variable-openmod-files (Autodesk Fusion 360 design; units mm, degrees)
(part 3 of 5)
sketch "Sketch1" plane through (0, 0, 1.5) normal (0, 0, 1) x axis (-1, 0, 0)
  line L1 (-6.5, -117.4019) -> (-9.9868, -115.3888)
  line L2 (-1, -130.9545) -> (-1, -126.9282)
  line L3 (-1, -107.0385) -> (-1, -103.0294)
  line L4 (-14.1969, -110.6487) -> (-10.725, -112.6532)
  line L5 (5.5, -115.6699) -> (8.9868, -113.6567)
  line L6 (-8.9868, -113.6567) -> (-5.5, -115.6699)
  line L7 (1, -132.9615) -> (1, -136.9706)
  line L8 (14.1969, -129.3513) -> (10.725, -127.3468)
  line L9 (11.725, -125.6147) -> (15.1969, -127.6193)
  line L10 (15.1969, -112.3807) -> (11.725, -114.3853)
  line L11 (-11.725, -114.3853) -> (-15.1969, -112.3807)
  line L12 (-15.1969, -127.6193) -> (-11.725, -125.6147)
  line L13 (-10.725, -127.3468) -> (-14.1969, -129.3513)
  line L14 (-1, -136.9706) -> (-1, -132.9615)
  line L15 (10.725, -112.6532) -> (14.1969, -110.6487)
  line L16 (1, -103.0294) -> (1, -107.0385)
  line L17 (1, -126.9282) -> (1, -130.9545)
  line L18 (9.9868, -115.3888) -> (6.5, -117.4019)
  line L19 (-16.1795, -137.7263) -> (-12.9621, -133.8919)
  line L20 (-11.43, -135.1775) -> (-14.6475, -139.0119)
  line L21 (-1, -143.9792) -> (-1, -138.9737)
  line L22 (1, -138.9737) -> (1, -143.9792)
  line L23 (14.6475, -139.0119) -> (11.43, -135.1775)
  line L24 (12.9621, -133.8919) -> (16.1795, -137.7263)
  line L25 (23.4412, -125.1487) -> (18.5118, -124.2796)
  line L26 (18.8591, -122.3099) -> (23.7885, -123.1791)
  line L27 (21.2666, -108.8764) -> (16.9317, -111.3792)
  line L28 (15.9317, -109.6471) -> (20.2666, -107.1444)
  line L29 (9.141, -97.809) -> (7.4291, -102.5126)
  line L30 (5.5497, -101.8286) -> (7.2617, -97.1249)
  line L31 (-7.2617, -97.1249) -> (-5.5497, -101.8286)
  line L32 (-7.4291, -102.5126) -> (-9.141, -97.809)
  line L33 (-20.2666, -107.1444) -> (-15.9317, -109.6471)
  line L34 (-16.9317, -111.3792) -> (-21.2666, -108.8764)
  line L35 (-23.7885, -123.1791) -> (-18.8591, -122.3099)
  line L36 (-18.5118, -124.2796) -> (-23.4412, -125.1487)
  arc A1 centre (0, -120) radius 7 clockwise from (-1, -126.9282) to (-6.5, -117.4019)
  arc A2 centre (0, -120) radius 11 clockwise from (-1, -130.9545) to (-9.9868, -115.3888)
  arc A3 centre (0, -120) radius 13 clockwise from (-10.725, -112.6532) to (-1, -107.0385)
  arc A4 centre (0, -120) radius 17 clockwise from (-14.1969, -110.6487) to (-1, -103.0294)
  circle C1 centre (0, -120) radius 5
  arc A5 centre (0, -120) radius 7 clockwise from (-5.5, -115.6699) to (5.5, -115.6699)
  arc A6 centre (0, -120) radius 11 clockwise from (-8.9868, -113.6567) to (8.9868, -113.6567)
  arc A7 centre (0, -120) radius 13 clockwise from (10.725, -127.3468) to (1, -132.9615)
  arc A8 centre (0, -120) radius 17 clockwise from (14.1969, -129.3513) to (1, -136.9706)
  arc A9 centre (0, -120) radius 17 clockwise from (15.1969, -112.3807) to (15.1969, -127.6193)
  arc A10 centre (0, -120) radius 13 clockwise from (11.725, -114.3853) to (11.725, -125.6147)
  arc A11 centre (0, -120) radius 17 clockwise from (-15.1969, -127.6193) to (-15.1969, -112.3807)
  arc A12 centre (0, -120) radius 13 clockwise from (-11.725, -125.6147) to (-11.725, -114.3853)
  arc A13 centre (0, -120) radius 17 clockwise from (-1, -136.9706) to (-14.1969, -129.3513)
  arc A14 centre (0, -120) radius 13 clockwise from (-1, -132.9615) to (-10.725, -127.3468)
  arc A15 centre (0, -120) radius 17 clockwise from (1, -103.0294) to (14.1969, -110.6487)
  arc A16 centre (0, -120) radius 13 clockwise from (1, -107.0385) to (10.725, -112.6532)
  arc A17 centre (0, -120) radius 7 clockwise from (6.5, -117.4019) to (1, -126.9282)
  arc A18 centre (0, -120) radius 11 clockwise from (9.9868, -115.3888) to (1, -130.9545)
  arc A19 centre (0, -120) radius 19 clockwise from (-12.9621, -133.8919) to (-18.5118, -124.2796)
  arc A20 centre (0, -120) radius 24 clockwise from (-14.6475, -139.0119) to (-16.1795, -137.7263)
  arc A21 centre (0, -120) radius 19 clockwise from (-1, -138.9737) to (-11.43, -135.1775)
  arc A22 centre (0, -120) radius 24 clockwise from (1, -143.9792) to (-1, -143.9792)
  arc A23 centre (0, -120) radius 19 clockwise from (11.43, -135.1775) to (1, -138.9737)
  arc A24 centre (0, -120) radius 24 clockwise from (16.1795, -137.7263) to (14.6475, -139.0119)
  arc A25 centre (0, -120) radius 19 clockwise from (18.5118, -124.2796) to (12.9621, -133.8919)
  arc A26 centre (0, -120) radius 24 clockwise from (23.7885, -123.1791) to (23.4412, -125.1487)
  arc A27 centre (0, -120) radius 19 clockwise from (16.9317, -111.3792) to (18.8591, -122.3099)
  arc A28 centre (0, -120) radius 24 clockwise from (20.2666, -107.1444) to (21.2666, -108.8764)
  arc A29 centre (0, -120) radius 19 clockwise from (7.4291, -102.5126) to (15.9317, -109.6471)
  arc A30 centre (0, -120) radius 24 clockwise from (7.2617, -97.1249) to (9.141, -97.809)
  arc A31 centre (0, -120) radius 19 clockwise from (-5.5497, -101.8286) to (5.5497, -101.8286)
  arc A32 centre (0, -120) radius 24 clockwise from (-9.141, -97.809) to (-7.2617, -97.1249)
  arc A33 centre (0, -120) radius 19 clockwise from (-15.9317, -109.6471) to (-7.4291, -102.5126)
  arc A34 centre (0, -120) radius 24 clockwise from (-21.2666, -108.8764) to (-20.2666, -107.1444)
  arc A35 centre (0, -120) radius 19 clockwise from (-18.8591, -122.3099) to (-16.9317, -111.3792)
  arc A36 centre (0, -120) radius 24 clockwise from (-23.4412, -125.1487) to (-23.7885, -123.1791)
  circle C2 centre (0, -120) radius 19
  concentric A1 C2
  dimension "d412" diameter C2 = 38
extrude "Extrude1" cut sketch "Sketch1" profile of L19 A20 L20 L21 A22 L22 L23 A24 L24 L25 A26 L26 L27 A28 L28 L29 A30 L30 L31 A32 L32 L33 A34 L34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 against normal blind 1.5 bodies "Pad Mount (1)"
sketch "Sketch2" plane through (0, 0, 0) normal (0, 0, -1) x axis (1, 0, 0)
  line L1 (9.9868, -115.3888) -> (6.5, -117.4019)
  line L2 (1, -126.9282) -> (1, -130.9545)
  line L3 (1, -103.0294) -> (1, -107.0385)
  line L4 (10.725, -112.6532) -> (14.1969, -110.6487)
  line L5 (-8.9868, -113.6567) -> (-5.5, -115.6699)
  line L6 (5.5, -115.6699) -> (8.9868, -113.6567)
  line L7 (-1, -136.9706) -> (-1, -132.9615)
  line L8 (-10.725, -127.3468) -> (-14.1969, -129.3513)
  line L9 (-11.725, -114.3853) -> (-15.1969, -112.3807)
  line L10 (-15.1969, -127.6193) -> (-11.725, -125.6147)
  line L11 (11.725, -125.6147) -> (15.1969, -127.6193)
  line L12 (15.1969, -112.3807) -> (11.725, -114.3853)
  line L13 (1, -132.9615) -> (1, -136.9706)
  line L14 (14.1969, -129.3513) -> (10.725, -127.3468)
  line L15 (-1, -107.0385) -> (-1, -103.0294)
  line L16 (-14.1969, -110.6487) -> (-10.725, -112.6532)
  line L17 (-1, -130.9545) -> (-1, -126.9282)
  line L18 (-6.5, -117.4019) -> (-9.9868, -115.3888)
  circle C1 centre (0, -120) radius 19
  arc A1 centre (0, -120) radius 11 clockwise from (9.9868, -115.3888) to (1, -130.9545)
  arc A2 centre (0, -120) radius 7 clockwise from (6.5, -117.4019) to (1, -126.9282)
  arc A3 centre (0, -120) radius 17 clockwise from (1, -103.0294) to (14.1969, -110.6487)
  arc A4 centre (0, -120) radius 13 clockwise from (1, -107.0385) to (10.725, -112.6532)
  circle C2 centre (0, -120) radius 5
  arc A5 centre (0, -120) radius 11 clockwise from (-8.9868, -113.6567) to (8.9868, -113.6567)
  arc A6 centre (0, -120) radius 7 clockwise from (-5.5, -115.6699) to (5.5, -115.6699)
  arc A7 centre (0, -120) radius 17 clockwise from (-1, -136.9706) to (-14.1969, -129.3513)
  arc A8 centre (0, -120) radius 13 clockwise from (-1, -132.9615) to (-10.725, -127.3468)
  arc A9 centre (0, -120) radius 17 clockwise from (-15.1969, -127.6193) to (-15.1969, -112.3807)
  arc A10 centre (0, -120) radius 13 clockwise from (-11.725, -125.6147) to (-11.725, -114.3853)
  arc A11 centre (0, -120) radius 17 clockwise from (15.1969, -112.3807) to (15.1969, -127.6193)
  arc A12 centre (0, -120) radius 13 clockwise from (11.725, -114.3853) to (11.725, -125.6147)
  arc A13 centre (0, -120) radius 17 clockwise from (14.1969, -129.3513) to (1, -136.9706)
  arc A14 centre (0, -120) radius 13 clockwise from (10.725, -127.3468) to (1, -132.9615)
  arc A15 centre (0, -120) radius 17 clockwise from (-14.1969, -110.6487) to (-1, -103.0294)
  arc A16 centre (0, -120) radius 13 clockwise from (-10.725, -112.6532) to (-1, -107.0385)
  arc A17 centre (0, -120) radius 11 clockwise from (-1, -130.9545) to (-9.9868, -115.3888)
  arc A18 centre (0, -120) radius 7 clockwise from (-1, -126.9282) to (-6.5, -117.4019)
  circle C3 centre (0, -120) radius 24
  circle C4 centre (0, -120) radius 20.5
  concentric C1 C3
  concentric C1 C4
  dimension "d415" diameter C3 = 48
  dimension "d416" diameter C4 = 41
extrude "Extrude2" add sketch "Sketch2" profile of C3 C4 against normal blind 2.5
extrude "Extrude3" add of existing geometry blind 2.5
extrude "Extrude4" add sketch "Sketch2" profile of C1 C4 against normal blind 2.5 bodies "Pad Mount (1)"
delete_face "DeleteFace1"
extrude "Extrude5" cut of existing geometry blind -4
sketch "Sketch3" plane through (0, 0, 22) normal (0, 0, 1) x axis (-1, 0, 0)
  line L1 (27.3973, -100.8162) -> (24.0432, -103.1648)
  line L2 (24.0432, -136.8352) -> (27.3973, -139.1838)
  line L3 (-8, -87.4692) -> (-8, -96.1036)
  line L4 (8, -96.1036) -> (8, -87.4692)
  line L5 (-27.3973, -139.1838) -> (-24.0432, -136.8352)
  line L6 (-24.0432, -103.1648) -> (-27.3973, -100.8162)
  line L7 (-8, -65.8761) -> (-8, -68.1306)
  line L8 (8, -68.1306) -> (8, -65.8761)
  line L9 (17.2573, -73.968) -> (18.1032, -72.1557)
  line L10 (6, -66.9692) -> (6, -69.7523)
  line L11 (-6, -66.9692) -> (6, -66.9692)
  line L12 (-6, -69.7523) -> (-6, -66.9692)
  line L13 (-18.1032, -72.1557) -> (-17.2573, -73.968)
  line L14 (-15.6326, -145.0174) -> (-17.7523, -148.4096)
  line L15 (17.7523, -148.4096) -> (15.6326, -145.0174)
  line L16 (8, -97) -> (8, -96.1036)
  line L17 (8, -101.1254) -> (8, -97)
  line L18 (-8, -101.1254) -> (-8, -96.1036)
  line L19 (20.5, -120) -> (0, -120)
  line L20 (15.9099, -104.0901) -> (0, -120)
  line L21 (22.5, -120) -> (0, -120)
  line L22 (-15.9099, -104.0901) -> (0, -120)
  line L23 (-22.5, -120) -> (0, -120)
  line L24 (44.7744, -114.5) -> (37, -114.5)
  line L25 (-37, -114.5) -> (-44.7744, -114.5)
  line L26 (-37, -125.5) -> (-37, -114.5)
  line L27 (-44.7744, -125.5) -> (-37, -125.5)
  line L28 (37, -125.5) -> (44.7744, -125.5)
  line L29 (37, -114.5) -> (37, -125.5)
  line L30 (40.4204, -134.6184) -> (31.8667, -135.2833)
  line L31 (40.0904, -135.7159) -> (40.4204, -134.6184)
  line L32 (33.9261, -136.0336) -> (40.0904, -135.7159)
  curve K1 (32.5509, -136.0589) -> (33.9261, -136.0336)
  curve K2 (33.681, -136.8488) -> (32.5509, -136.0589)
  line L33 (38.6244, -140.5917) -> (33.681, -136.8488)
  line L34 (38.3133, -141.6264) -> (38.6244, -140.5917)
  line L35 (31.554, -136.3233) -> (38.3133, -141.6264)
  line L36 (31.8667, -135.2833) -> (31.554, -136.3233)
  line L37 (30.457, -152.0325) -> (25.6804, -148.7507)
  line L38 (29.9007, -152.8421) -> (30.457, -152.0325)
  line L39 (25.1241, -149.5603) -> (29.9007, -152.8421)
  line L40 (25.6804, -148.7507) -> (25.1241, -149.5603)
  line L41 (-27.2839, -159.541) -> (-19.3124, -156.3956)
  line L42 (-28.0551, -158.7007) -> (-27.2839, -159.541)
  line L43 (-24.3746, -150.8793) -> (-28.0551, -158.7007)
  line L44 (-23.5592, -151.7679) -> (-24.3746, -150.8793)
  line L45 (-24.7134, -154.0936) -> (-23.5592, -151.7679)
  line L46 (-22.4517, -156.5582) -> (-24.7134, -154.0936)
  line L47 (-20.0725, -155.5673) -> (-22.4517, -156.5582)
  line L48 (-19.3124, -156.3956) -> (-20.0725, -155.5673)
  line L49 (-35.6785, -142.0432) -> (-30.2699, -139.9615)
  line L50 (-36.0313, -141.1265) -> (-35.6785, -142.0432)
  line L51 (-30.6227, -139.0448) -> (-36.0313, -141.1265)
  line L52 (-30.2699, -139.9615) -> (-30.6227, -139.0448)
  line L53 (-37.736, -142.8351) -> (-36.6818, -142.4293)
  line L54 (-38.0888, -141.9183) -> (-37.736, -142.8351)
  line L55 (-37.0346, -141.5126) -> (-38.0888, -141.9183)
  line L56 (-36.6818, -142.4293) -> (-37.0346, -141.5126)
  line L57 (-18.3117, -159.6909) -> (-17.5657, -160.3171)
  curve K3 (-16.7865, -158.8106) -> (-18.3117, -159.6909)
  curve K4 (-15.133, -159.1979) -> (-16.7865, -158.8106)
  curve K5 (-13.9409, -160.8837) -> (-15.133, -159.1979)
  curve K6 (-14.5331, -163.1512) -> (-13.9409, -160.8837)
  curve K7 (-15.6803, -164.3672) -> (-14.5331, -163.1512)
  curve K8 (-17.0469, -164.7465) -> (-15.6803, -164.3672)
  curve K9 (-18.4019, -164.2975) -> (-17.0469, -164.7465)
  curve K10 (-19.4455, -163.063) -> (-18.4019, -164.2975)
  curve K11 (-19.3628, -161.506) -> (-19.4455, -163.063)
  line L58 (-18.479, -161.8966) -> (-19.3628, -161.506)
  curve K12 (-18.5456, -162.8969) -> (-18.479, -161.8966)
  curve K13 (-17.9988, -163.5965) -> (-18.5456, -162.8969)
  curve K14 (-16.6962, -163.7983) -> (-17.9988, -163.5965)
  curve K15 (-15.3982, -162.6301) -> (-16.6962, -163.7983)
  curve K16 (-14.8606, -160.9594) -> (-15.3982, -162.6301)
  curve K17 (-15.559, -159.8841) -> (-14.8606, -160.9594)
  curve K18 (-16.5638, -159.6624) -> (-15.559, -159.8841)
  curve K19 (-17.5657, -160.3171) -> (-16.5638, -159.6624)
  curve K20 (29.3301, -142.3161) -> (29.4979, -143.5426)
  curve K21 (29.5989, -141.2495) -> (29.3301, -142.3161)
  curve K22 (30.6252, -140.1009) -> (29.5989, -141.2495)
  curve K23 (31.923, -140.1206) -> (30.6252, -140.1009)
  curve K24 (32.5534, -140.6155) -> (31.923, -140.1206)
  curve K25 (32.8611, -141.3096) -> (32.5534, -140.6155)
  curve K26 (32.8658, -142.0862) -> (32.8611, -141.3096)
  curve K27 (32.6431, -142.9432) -> (32.8658, -142.0862)
  curve K28 (32.2353, -144.68) -> (32.6431, -142.9432)
  curve K29 (32.4671, -144.7899) -> (32.2353, -144.68)
  curve K30 (33.3528, -144.882) -> (32.4671, -144.7899)
  curve K31 (34.1141, -143.9973) -> (33.3528, -144.882)
  curve K32 (34.3111, -142.9643) -> (34.1141, -143.9973)
  curve K33 (33.7266, -142.1671) -> (34.3111, -142.9643)
  line L59 (34.239, -141.3443) -> (33.7266, -142.1671)
  curve K34 (34.9714, -142.145) -> (34.239, -141.3443)
  curve K35 (35.1493, -143.1756) -> (34.9714, -142.145)
  curve K36 (34.7981, -144.4594) -> (35.1493, -143.1756)
  curve K37 (34.1454, -145.4885) -> (34.7981, -144.4594)
  curve K38 (33.4655, -145.9312) -> (34.1454, -145.4885)
  curve K39 (32.7305, -145.9366) -> (33.4655, -145.9312)
  curve K40 (31.8838, -145.6108) -> (32.7305, -145.9366)
  line L60 (30.6887, -145.0751) -> (31.8838, -145.6108)
  curve K41 (29.082, -144.4236) -> (30.6887, -145.0751)
  curve K42 (28.3455, -144.3655) -> (29.082, -144.4236)
  line L61 (28.7652, -143.4294) -> (28.3455, -144.3655)
  curve K43 (29.4979, -143.5426) -> (28.7652, -143.4294)
  curve K44 (-36.4141, -138.56) -> (-33.8745, -138.7564)
  curve K45 (-37.5395, -136.9883) -> (-36.4141, -138.56)
  curve K46 (-37.3306, -134.894) -> (-37.5395, -136.9883)
  curve K47 (-35.4632, -133.5636) -> (-37.3306, -134.894)
  curve K48 (-33.6794, -133.3966) -> (-35.4632, -133.5636)
  curve K49 (-32.4511, -134.0579) -> (-33.6794, -133.3966)
  curve K50 (-31.7211, -135.3037) -> (-32.4511, -134.0579)
  curve K51 (-31.9236, -137.4104) -> (-31.7211, -135.3037)
  curve K52 (-33.8745, -138.7564) -> (-31.9236, -137.4104)
  line L62 (20.5824, -155.057) -> (19.8923, -155.6522)
  line L63 (25.8075, -161.1149) -> (20.5824, -155.057)
  line L64 (25.0636, -161.7565) -> (25.8075, -161.1149)
  line L65 (23.1996, -159.5953) -> (25.0636, -161.7565)
  curve K53 (22.5068, -161.2234) -> (23.1996, -159.5953)
  curve K54 (21.5994, -161.7213) -> (22.5068, -161.2234)
  curve K55 (20.6088, -161.7759) -> (21.5994, -161.7213)
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  point P10 (8, -96.1036)
  point P40 (8, -96.1036)
  point P9 (-8, -96.1036)
  point P43 (-8, -96.1036)
  point P4 (0, -120)
  point P46 (0, -120)
  point P49 (0, -120)
  point P45 (0, -120)
  point P52 (0, -120)
  coincident P10 P40
  parallel L4 L17
  coincident P9 P43
  parallel L3 L18
  horizontal L19
  coincident P4 P46
  horizontal L21
  coincident P4 P49
  horizontal L23
  coincident P45 P52
  dimension "d425" diameter = 41
  dimension "d426" diameter = 32
  dimension "d428" diameter = 45
  dimension "d429" angle L20 L21 = 45
  dimension "d430" angle L22 L23 = 45
extrude "Extrude6" add sketch "Sketch3" against normal blind 2
extrude "Extrude7" add sketch "Sketch3" along normal blind 4
chamfer "Chamfer1" distance 4.5 Rotate Angle 40
chamfer "Chamfer2" distance 4 Rotate Angle 45
copy_paste_bodies "CopyPasteBodies2"
move "Move1"
delete_face "DeleteFace2"
extrude "Extrude8" cut of existing geometry blind -4
offset_faces "OffsetFaces1" distance 1
offset_faces "OffsetFaces2" distance -1
delete_face "DeleteFace3"
offset_faces "OffsetFaces3" distance 1
offset_faces "OffsetFaces4" distance -1
sketch "Sketch4" plane through (0, 0, 22) normal (0, 0, 1) x axis (-1, 0, 0)
  line L1 (-127.3973, -19.1838) -> (-124.8888, -17.4274)
  line L2 (-124.8888, 17.4274) -> (-127.3973, 19.1838)
  curve K1 (-124.8888, 17.4274) -> (-124.8888, -17.4274)
  line L3 (-115.6326, -25.0174) -> (-117.7523, -28.4096)
  line L4 (-82.2477, -28.4096) -> (-84.3674, -25.0174)
  line L5 (-108, 54.1239) -> (-108, 51.8694)
  line L6 (-92, 51.8694) -> (-92, 54.1239)
  line L7 (-82.7427, 46.032) -> (-81.8968, 47.8443)
  line L8 (-94, 53.0308) -> (-94, 50.2477)
  line L9 (-106, 53.0308) -> (-94, 53.0308)
  line L10 (-106, 50.2477) -> (-106, 53.0308)
  line L11 (-118.1032, 47.8443) -> (-117.2573, 46.032)
  line L12 (-72.6027, 19.1838) -> (-75.1112, 17.4274)
  line L13 (-75.1112, -17.4274) -> (-72.6027, -19.1838)
  curve K2 (-75.1112, -17.4274) -> (-75.1112, 17.4274)
  line L14 (-108, 32.5308) -> (-108, 24.9487)
  line L15 (-92, 24.9487) -> (-92, 32.5308)
  line L16 (-79.706, 20.294) -> (-100, 0)
  line L17 (-71.3, 0) -> (-100, 0)
  line L18 (-120.294, 20.294) -> (-100, 0)
  line L19 (-128.7, 0) -> (-100, 0)
  line L20 (-55.2256, 5.5) -> (-63, 5.5)
  line L21 (-137, 5.5) -> (-144.7744, 5.5)
  line L22 (-137, -5.5) -> (-137, 5.5)
  line L23 (-144.7744, -5.5) -> (-137, -5.5)
  line L24 (-63, -5.5) -> (-55.2256, -5.5)
  line L25 (-63, 5.5) -> (-63, -5.5)
  line L26 (-59.5796, -14.6184) -> (-68.1333, -15.2833)
  line L27 (-59.9096, -15.7159) -> (-59.5796, -14.6184)
  line L28 (-66.0739, -16.0336) -> (-59.9096, -15.7159)
  curve K3 (-67.4491, -16.0589) -> (-66.0739, -16.0336)
  curve K4 (-66.319, -16.8488) -> (-67.4491, -16.0589)
  line L29 (-61.3756, -20.5917) -> (-66.319, -16.8488)
  line L30 (-61.6867, -21.6264) -> (-61.3756, -20.5917)
  line L31 (-68.446, -16.3233) -> (-61.6867, -21.6264)
  line L32 (-68.1333, -15.2833) -> (-68.446, -16.3233)
  line L33 (-69.543, -32.0325) -> (-74.3196, -28.7507)
  line L34 (-70.0993, -32.8421) -> (-69.543, -32.0325)
  line L35 (-74.8759, -29.5603) -> (-70.0993, -32.8421)
  line L36 (-74.3196, -28.7507) -> (-74.8759, -29.5603)
  line L37 (-127.2839, -39.541) -> (-119.3124, -36.3956)
  line L38 (-128.0551, -38.7007) -> (-127.2839, -39.541)
  line L39 (-124.3746, -30.8793) -> (-128.0551, -38.7007)
  line L40 (-123.5592, -31.7679) -> (-124.3746, -30.8793)
  line L41 (-124.7134, -34.0936) -> (-123.5592, -31.7679)
  line L42 (-122.4517, -36.5582) -> (-124.7134, -34.0936)
  line L43 (-120.0725, -35.5673) -> (-122.4517, -36.5582)
  line L44 (-119.3124, -36.3956) -> (-120.0725, -35.5673)
  line L45 (-135.6785, -22.0432) -> (-130.2699, -19.9615)
  line L46 (-136.0313, -21.1265) -> (-135.6785, -22.0432)
  line L47 (-130.6227, -19.0448) -> (-136.0313, -21.1265)
  line L48 (-130.2699, -19.9615) -> (-130.6227, -19.0448)
  line L49 (-137.736, -22.8351) -> (-136.6818, -22.4293)
  line L50 (-138.0888, -21.9183) -> (-137.736, -22.8351)
  line L51 (-137.0346, -21.5126) -> (-138.0888, -21.9183)
  line L52 (-136.6818, -22.4293) -> (-137.0346, -21.5126)
  line L53 (-118.3117, -39.6909) -> (-117.5657, -40.3171)
  curve K5 (-116.7865, -38.8106) -> (-118.3117, -39.6909)
  curve K6 (-115.133, -39.1979) -> (-116.7865, -38.8106)
  curve K7 (-113.9409, -40.8837) -> (-115.133, -39.1979)
  curve K8 (-114.5331, -43.1512) -> (-113.9409, -40.8837)
  curve K9 (-115.6803, -44.3672) -> (-114.5331, -43.1512)
  curve K10 (-117.0469, -44.7465) -> (-115.6803, -44.3672)
  curve K11 (-118.4019, -44.2975) -> (-117.0469, -44.7465)
  curve K12 (-119.4455, -43.063) -> (-118.4019, -44.2975)
  curve K13 (-119.3628, -41.506) -> (-119.4455, -43.063)
  line L54 (-118.479, -41.8966) -> (-119.3628, -41.506)
  curve K14 (-118.5456, -42.8969) -> (-118.479, -41.8966)
  curve K15 (-117.9988, -43.5965) -> (-118.5456, -42.8969)
  curve K16 (-116.6962, -43.7983) -> (-117.9988, -43.5965)
  curve K17 (-115.3982, -42.6301) -> (-116.6962, -43.7983)
  curve K18 (-114.8606, -40.9594) -> (-115.3982, -42.6301)
  curve K19 (-115.559, -39.8841) -> (-114.8606, -40.9594)
  curve K20 (-116.5638, -39.6624) -> (-115.559, -39.8841)
  curve K21 (-117.5657, -40.3171) -> (-116.5638, -39.6624)
  curve K22 (-70.6699, -22.3161) -> (-70.5021, -23.5426)
  curve K23 (-70.4011, -21.2495) -> (-70.6699, -22.3161)
  curve K24 (-69.3748, -20.1009) -> (-70.4011, -21.2495)
  curve K25 (-68.077, -20.1206) -> (-69.3748, -20.1009)
  curve K26 (-67.4466, -20.6155) -> (-68.077, -20.1206)
  curve K27 (-67.1389, -21.3096) -> (-67.4466, -20.6155)
  curve K28 (-67.1342, -22.0862) -> (-67.1389, -21.3096)
  curve K29 (-67.3569, -22.9432) -> (-67.1342, -22.0862)
  curve K30 (-67.7647, -24.68) -> (-67.3569, -22.9432)
  curve K31 (-67.5329, -24.7899) -> (-67.7647, -24.68)
  curve K32 (-66.6472, -24.882) -> (-67.5329, -24.7899)
  curve K33 (-65.8859, -23.9973) -> (-66.6472, -24.882)
  curve K34 (-65.6889, -22.9643) -> (-65.8859, -23.9973)
  curve K35 (-66.2734, -22.1671) -> (-65.6889, -22.9643)
  line L55 (-65.761, -21.3443) -> (-66.2734, -22.1671)
  curve K36 (-65.0286, -22.145) -> (-65.761, -21.3443)
  curve K37 (-64.8507, -23.1756) -> (-65.0286, -22.145)
  curve K38 (-65.2019, -24.4594) -> (-64.8507, -23.1756)
  curve K39 (-65.8546, -25.4885) -> (-65.2019, -24.4594)
  curve K40 (-66.5345, -25.9312) -> (-65.8546, -25.4885)
  curve K41 (-67.2695, -25.9366) -> (-66.5345, -25.9312)
  curve K42 (-68.1162, -25.6108) -> (-67.2695, -25.9366)
  line L56 (-69.3113, -25.0751) -> (-68.1162, -25.6108)
  curve K43 (-70.918, -24.4236) -> (-69.3113, -25.0751)
  curve K44 (-71.6545, -24.3655) -> (-70.918, -24.4236)
  line L57 (-71.2348, -23.4294) -> (-71.6545, -24.3655)
  curve K45 (-70.5021, -23.5426) -> (-71.2348, -23.4294)
  curve K46 (-136.4141, -18.56) -> (-133.8745, -18.7564)
  curve K47 (-137.5395, -16.9883) -> (-136.4141, -18.56)
  curve K48 (-137.3306, -14.894) -> (-137.5395, -16.9883)
  curve K49 (-135.4632, -13.5636) -> (-137.3306, -14.894)
  curve K50 (-133.6794, -13.3966) -> (-135.4632, -13.5636)
  curve K51 (-132.4511, -14.0579) -> (-133.6794, -13.3966)
  curve K52 (-131.7211, -15.3037) -> (-132.4511, -14.0579)
  curve K53 (-131.9236, -17.4104) -> (-131.7211, -15.3037)
  curve K54 (-133.8745, -18.7564) -> (-131.9236, -17.4104)
  line L58 (-79.4176, -35.057) -> (-80.1077, -35.6522)
  line L59 (-74.1925, -41.1149) -> (-79.4176, -35.057)
  line L60 (-74.9364, -41.7565) -> (-74.1925, -41.1149)
  line L61 (-76.8004, -39.5953) -> (-74.9364, -41.7565)
  curve K55 (-77.4932, -41.2234) -> (-76.8004, -39.5953)
  curve K56 (-78.4006, -41.7213) -> (-77.4932, -41.2234)
  curve K57 (-79.3912, -41.7759) -> (-78.4006, -41.7213)
  curve K58 (-80.3718, -41.3785) -> (-79.3912, -41.7759)
  curve K59 (-81.2739, -40.6) -> (-80.3718, -41.3785)
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  point P35 (-100, 0)
  point P38 (-100, 0)
  point P5 (-100, 0)
  point P41 (-100, 0)
  horizontal L17
  coincident P35 P38
  horizontal L19
  coincident P5 P41
  dimension "d445" diameter = 42
  dimension "d446" diameter = 52.4
  dimension "d449" diameter = 57.4
  dimension "d452" angle L16 L17 = 45
  dimension "d453" angle L18 L19 = 45
extrude "Extrude9" add sketch "Sketch4" against normal blind 2
extrude "Extrude10" add sketch "Sketch4" along normal blind 5
chamfer "Chamfer3" distance 5.2 Rotate Angle 40
chamfer "Chamfer4" distance 5 Rotate Angle 45
offset_faces "OffsetFaces5" distance 5
offset_faces "OffsetFaces8" distance 1
offset_faces "OffsetFaces9" distance -1
copy_paste_bodies "CopyPasteBodies3"
move "Move2"
copy_paste_bodies "CopyPasteBodies4"
move "Move3"
delete_face "DeleteFace4"
extrude "Extrude11" cut of existing geometry blind -4
offset_faces "OffsetFaces10" distance 3
offset_faces "OffsetFaces11" distance 2.5
offset_faces "OffsetFaces12" distance 3
offset_faces "OffsetFaces13" distance 2.5
sketch "Sketch5" plane through (0, 0, 22) normal (0, 0, 1) x axis (-1, 0, 0)
  line L1 (-72.6027, -100.8162) -> (-75.9568, -103.1648)
  line L2 (-75.9568, -136.8352) -> (-72.6027, -139.1838)
  line L3 (-108, -87.4692) -> (-108, -99.2915)
  line L4 (-92, -99.2915) -> (-92, -87.4692)
  line L5 (-127.3973, -139.1838) -> (-124.0432, -136.8352)
  line L6 (-124.0432, -103.1648) -> (-127.3973, -100.8162)
  line L7 (-108, -65.8761) -> (-108, -68.1306)
  line L8 (-92, -68.1306) -> (-92, -65.8761)
  line L9 (-82.7427, -73.968) -> (-81.8968, -72.1557)
  line L10 (-94, -66.9692) -> (-94, -69.7523)
  line L11 (-106, -66.9692) -> (-94, -66.9692)
  line L12 (-106, -69.7523) -> (-106, -66.9692)
  line L13 (-118.1032, -72.1557) -> (-117.2573, -73.968)
  line L14 (-115.6326, -145.0174) -> (-117.7523, -148.4096)
  line L15 (-82.2477, -148.4096) -> (-84.3674, -145.0174)
  line L16 (-82.888, -102.888) -> (-100, -120)
  line L17 (-75.8, -120) -> (-100, -120)
  line L18 (-117.112, -102.888) -> (-100, -120)
  line L19 (-124.2, -120) -> (-100, -120)
  line L20 (-55.2256, -114.5) -> (-63, -114.5)
  line L21 (-137, -114.5) -> (-144.7744, -114.5)
  line L22 (-137, -125.5) -> (-137, -114.5)
  line L23 (-144.7744, -125.5) -> (-137, -125.5)
  line L24 (-63, -125.5) -> (-55.2256, -125.5)
  line L25 (-63, -114.5) -> (-63, -125.5)
  line L26 (-59.5796, -134.6184) -> (-68.1333, -135.2833)
  line L27 (-59.9096, -135.7159) -> (-59.5796, -134.6184)
  line L28 (-66.0739, -136.0336) -> (-59.9096, -135.7159)
  curve K1 (-67.4491, -136.0589) -> (-66.0739, -136.0336)
  curve K2 (-66.319, -136.8488) -> (-67.4491, -136.0589)
  line L29 (-61.3756, -140.5917) -> (-66.319, -136.8488)
  line L30 (-61.6867, -141.6264) -> (-61.3756, -140.5917)
  line L31 (-68.446, -136.3233) -> (-61.6867, -141.6264)
  line L32 (-68.1333, -135.2833) -> (-68.446, -136.3233)
  line L33 (-69.543, -152.0325) -> (-74.3196, -148.7507)
  line L34 (-70.0993, -152.8421) -> (-69.543, -152.0325)
  line L35 (-74.8759, -149.5603) -> (-70.0993, -152.8421)
  line L36 (-74.3196, -148.7507) -> (-74.8759, -149.5603)
  line L37 (-127.2839, -159.541) -> (-119.3124, -156.3956)
  line L38 (-128.0551, -158.7007) -> (-127.2839, -159.541)
  line L39 (-124.3746, -150.8793) -> (-128.0551, -158.7007)
  line L40 (-123.5592, -151.7679) -> (-124.3746, -150.8793)
  line L41 (-124.7134, -154.0936) -> (-123.5592, -151.7679)
  line L42 (-122.4517, -156.5582) -> (-124.7134, -154.0936)
  line L43 (-120.0725, -155.5673) -> (-122.4517, -156.5582)
  line L44 (-119.3124, -156.3956) -> (-120.0725, -155.5673)
  line L45 (-135.6785, -142.0432) -> (-130.2699, -139.9615)
  line L46 (-136.0313, -141.1265) -> (-135.6785, -142.0432)
  line L47 (-130.6227, -139.0448) -> (-136.0313, -141.1265)
  line L48 (-130.2699, -139.9615) -> (-130.6227, -139.0448)
  line L49 (-137.736, -142.8351) -> (-136.6818, -142.4293)
  line L50 (-138.0888, -141.9183) -> (-137.736, -142.8351)
  line L51 (-137.0346, -141.5126) -> (-138.0888, -141.9183)
  line L52 (-136.6818, -142.4293) -> (-137.0346, -141.5126)
  line L53 (-118.3117, -159.6909) -> (-117.5657, -160.3171)
  curve K3 (-116.7865, -158.8106) -> (-118.3117, -159.6909)
  curve K4 (-115.133, -159.1979) -> (-116.7865, -158.8106)
  curve K5 (-113.9409, -160.8837) -> (-115.133, -159.1979)
  curve K6 (-114.5331, -163.1512) -> (-113.9409, -160.8837)
  curve K7 (-115.6803, -164.3672) -> (-114.5331, -163.1512)
  curve K8 (-117.0469, -164.7465) -> (-115.6803, -164.3672)
  curve K9 (-118.4019, -164.2975) -> (-117.0469, -164.7465)
  curve K10 (-119.4455, -163.063) -> (-118.4019, -164.2975)
  curve K11 (-119.3628, -161.506) -> (-119.4455, -163.063)
  line L54 (-118.479, -161.8966) -> (-119.3628, -161.506)
  curve K12 (-118.5456, -162.8969) -> (-118.479, -161.8966)
  curve K13 (-117.9988, -163.5965) -> (-118.5456, -162.8969)
  curve K14 (-116.6962, -163.7983) -> (-117.9988, -163.5965)
  curve K15 (-115.3982, -162.6301) -> (-116.6962, -163.7983)
  curve K16 (-114.8606, -160.9594) -> (-115.3982, -162.6301)
  curve K17 (-115.559, -159.8841) -> (-114.8606, -160.9594)
  curve K18 (-116.5638, -159.6624) -> (-115.559, -159.8841)
  curve K19 (-117.5657, -160.3171) -> (-116.5638, -159.6624)
  curve K20 (-70.6699, -142.3161) -> (-70.5021, -143.5426)
  curve K21 (-70.4011, -141.2495) -> (-70.6699, -142.3161)
  curve K22 (-69.3748, -140.1009) -> (-70.4011, -141.2495)
  curve K23 (-68.077, -140.1206) -> (-69.3748, -140.1009)
  curve K24 (-67.4466, -140.6155) -> (-68.077, -140.1206)
  curve K25 (-67.1389, -141.3096) -> (-67.4466, -140.6155)
  curve K26 (-67.1342, -142.0862) -> (-67.1389, -141.3096)
  curve K27 (-67.3569, -142.9432) -> (-67.1342, -142.0862)
  curve K28 (-67.7647, -144.68) -> (-67.3569, -142.9432)
  curve K29 (-67.5329, -144.7899) -> (-67.7647, -144.68)
  curve K30 (-66.6472, -144.882) -> (-67.5329, -144.7899)
  curve K31 (-65.8859, -143.9973) -> (-66.6472, -144.882)
  curve K32 (-65.6889, -142.9643) -> (-65.8859, -143.9973)
  curve K33 (-66.2734, -142.1671) -> (-65.6889, -142.9643)
  line L55 (-65.761, -141.3443) -> (-66.2734, -142.1671)
  curve K34 (-65.0286, -142.145) -> (-65.761, -141.3443)
  curve K35 (-64.8507, -143.1756) -> (-65.0286, -142.145)
  curve K36 (-65.2019, -144.4594) -> (-64.8507, -143.1756)
  curve K37 (-65.8546, -145.4885) -> (-65.2019, -144.4594)
  curve K38 (-66.5345, -145.9312) -> (-65.8546, -145.4885)
  curve K39 (-67.2695, -145.9366) -> (-66.5345, -145.9312)
  curve K40 (-68.1162, -145.6108) -> (-67.2695, -145.9366)
  line L56 (-69.3113, -145.0751) -> (-68.1162, -145.6108)
  curve K41 (-70.918, -144.4236) -> (-69.3113, -145.0751)
  curve K42 (-71.6545, -144.3655) -> (-70.918, -144.4236)
  line L57 (-71.2348, -143.4294) -> (-71.6545, -144.3655)
  curve K43 (-70.5021, -143.5426) -> (-71.2348, -143.4294)
  curve K44 (-136.4141, -138.56) -> (-133.8745, -138.7564)
  curve K45 (-137.5395, -136.9883) -> (-136.4141, -138.56)
  curve K46 (-137.3306, -134.894) -> (-137.5395, -136.9883)
  curve K47 (-135.4632, -133.5636) -> (-137.3306, -134.894)
  curve K48 (-133.6794, -133.3966) -> (-135.4632, -133.5636)
  curve K49 (-132.4511, -134.0579) -> (-133.6794, -133.3966)
  curve K50 (-131.7211, -135.3037) -> (-132.4511, -134.0579)
  curve K51 (-131.9236, -137.4104) -> (-131.7211, -135.3037)
  curve K52 (-133.8745, -138.7564) -> (-131.9236, -137.4104)
  line L58 (-79.4176, -155.057) -> (-80.1077, -155.6522)
  line L59 (-74.1925, -161.1149) -> (-79.4176, -155.057)
  line L60 (-74.9364, -161.7565) -> (-74.1925, -161.1149)
  line L61 (-76.8004, -159.5953) -> (-74.9364, -161.7565)
  curve K53 (-77.4932, -161.2234) -> (-76.8004, -159.5953)
  curve K54 (-78.4006, -161.7213) -> (-77.4932, -161.2234)
  curve K55 (-79.3912, -161.7759) -> (-78.4006, -161.7213)
  curve K56 (-80.3718, -161.3785) -> (-79.3912, -161.7759)
  curve K57 (-81.2739, -160.6) -> (-80.3718, -161.3785)
  curve K58 (-82.2201, -158.375) -> (-81.2739, -160.6)
  curve K59 (-81.4123, -156.6045) -> (-82.2201, -158.375)
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  point P4 (-100, -120)
  point P41 (-100, -120)
  point P40 (-100, -120)
  point P44 (-100, -120)
  horizontal L17
  coincident P4 P41
  horizontal L19
  coincident P40 P44
  dimension "d471" diameter = 48.4
  dimension "d472" diameter = 36
  dimension "d473" angle L16 L17 = 45
  dimension "d474" angle L18 L19 = 45
extrude "Extrude12" add sketch "Sketch5" along normal blind 4
chamfer "Chamfer5" distance 4.2 Rotate Angle 40
chamfer "Chamfer6" distance 4 Rotate Angle 45
sketch "Sketch6" plane through (0, 0, 22) normal (0, 0, 1) x axis (-1, 0, 0)
  line L1 (-172.6027, -100.8162) -> (-175.9568, -103.1648)
  line L2 (-175.9568, -136.8352) -> (-172.6027, -139.1838)
  line L3 (-208, -87.4692) -> (-208, -98.7564)
  line L4 (-192, -98.7564) -> (-192, -87.4692)
  line L5 (-227.3973, -139.1838) -> (-224.0432, -136.8352)
  line L6 (-224.0432, -103.1648) -> (-227.3973, -100.8162)
  line L7 (-208, -65.8761) -> (-208, -68.1306)
  line L8 (-192, -68.1306) -> (-192, -65.8761)
  line L9 (-182.7427, -73.968) -> (-181.8968, -72.1557)
  line L10 (-194, -66.9692) -> (-194, -69.7523)
  line L11 (-206, -66.9692) -> (-194, -66.9692)
  line L12 (-206, -69.7523) -> (-206, -66.9692)
  line L13 (-218.1032, -72.1557) -> (-217.2573, -73.968)
  line L14 (-215.6326, -145.0174) -> (-217.7523, -148.4096)
  line L15 (-182.2477, -148.4096) -> (-184.3674, -145.0174)
  line L16 (-182.5345, -102.5345) -> (-200, -120)
  line L17 (-175.3, -120) -> (-200, -120)
  line L18 (-217.4655, -102.5345) -> (-200, -120)
  line L19 (-224.7, -120) -> (-200, -120)
  line L20 (-155.2256, -114.5) -> (-163, -114.5)
  line L21 (-237, -114.5) -> (-244.7744, -114.5)
  line L22 (-237, -125.5) -> (-237, -114.5)
  line L23 (-244.7744, -125.5) -> (-237, -125.5)
  line L24 (-163, -125.5) -> (-155.2256, -125.5)
  line L25 (-163, -114.5) -> (-163, -125.5)
  line L26 (-159.5796, -134.6184) -> (-168.1333, -135.2833)
  line L27 (-159.9096, -135.7159) -> (-159.5796, -134.6184)
  line L28 (-166.0739, -136.0336) -> (-159.9096, -135.7159)
  curve K1 (-167.4491, -136.0589) -> (-166.0739, -136.0336)
  curve K2 (-166.319, -136.8488) -> (-167.4491, -136.0589)
  line L29 (-161.3756, -140.5917) -> (-166.319, -136.8488)
  line L30 (-161.6867, -141.6264) -> (-161.3756, -140.5917)
  line L31 (-168.446, -136.3233) -> (-161.6867, -141.6264)
  line L32 (-168.1333, -135.2833) -> (-168.446, -136.3233)
  line L33 (-169.543, -152.0325) -> (-174.3196, -148.7507)
  line L34 (-170.0993, -152.8421) -> (-169.543, -152.0325)
  line L35 (-174.8759, -149.5603) -> (-170.0993, -152.8421)
  line L36 (-174.3196, -148.7507) -> (-174.8759, -149.5603)
  line L37 (-227.2839, -159.541) -> (-219.3124, -156.3956)
  line L38 (-228.0551, -158.7007) -> (-227.2839, -159.541)
  line L39 (-224.3746, -150.8793) -> (-228.0551, -158.7007)
  line L40 (-223.5592, -151.7679) -> (-224.3746, -150.8793)
  line L41 (-224.7134, -154.0936) -> (-223.5592, -151.7679)
  line L42 (-222.4517, -156.5582) -> (-224.7134, -154.0936)
  line L43 (-220.0725, -155.5673) -> (-222.4517, -156.5582)
  line L44 (-219.3124, -156.3956) -> (-220.0725, -155.5673)
  line L45 (-235.6785, -142.0432) -> (-230.2699, -139.9615)
  line L46 (-236.0313, -141.1265) -> (-235.6785, -142.0432)
  line L47 (-230.6227, -139.0448) -> (-236.0313, -141.1265)
  line L48 (-230.2699, -139.9615) -> (-230.6227, -139.0448)
  line L49 (-237.736, -142.8351) -> (-236.6818, -142.4293)
  line L50 (-238.0888, -141.9183) -> (-237.736, -142.8351)
  line L51 (-237.0346, -141.5126) -> (-238.0888, -141.9183)
  line L52 (-236.6818, -142.4293) -> (-237.0346, -141.5126)
  line L53 (-218.3117, -159.6909) -> (-217.5657, -160.3171)
  curve K3 (-216.7865, -158.8106) -> (-218.3117, -159.6909)
  curve K4 (-215.133, -159.1979) -> (-216.7865, -158.8106)
  curve K5 (-213.9409, -160.8837) -> (-215.133, -159.1979)
  curve K6 (-214.5331, -163.1512) -> (-213.9409, -160.8837)
  curve K7 (-215.6803, -164.3672) -> (-214.5331, -163.1512)
  curve K8 (-217.0469, -164.7465) -> (-215.6803, -164.3672)
  curve K9 (-218.4019, -164.2975) -> (-217.0469, -164.7465)
  curve K10 (-219.4455, -163.063) -> (-218.4019, -164.2975)
  curve K11 (-219.3628, -161.506) -> (-219.4455, -163.063)
  line L54 (-218.479, -161.8966) -> (-219.3628, -161.506)
  curve K12 (-218.5456, -162.8969) -> (-218.479, -161.8966)
  curve K13 (-217.9988, -163.5965) -> (-218.5456, -162.8969)
  curve K14 (-216.6962, -163.7983) -> (-217.9988, -163.5965)
  curve K15 (-215.3982, -162.6301) -> (-216.6962, -163.7983)
  curve K16 (-214.8606, -160.9594) -> (-215.3982, -162.6301)
  curve K17 (-215.559, -159.8841) -> (-214.8606, -160.9594)
  curve K18 (-216.5638, -159.6624) -> (-215.559, -159.8841)
  curve K19 (-217.5657, -160.3171) -> (-216.5638, -159.6624)
  curve K20 (-170.6699, -142.3161) -> (-170.5021, -143.5426)
  curve K21 (-170.4011, -141.2495) -> (-170.6699, -142.3161)
  curve K22 (-169.3748, -140.1009) -> (-170.4011, -141.2495)
  curve K23 (-168.077, -140.1206) -> (-169.3748, -140.1009)
  curve K24 (-167.4466, -140.6155) -> (-168.077, -140.1206)
  curve K25 (-167.1389, -141.3096) -> (-167.4466, -140.6155)
  curve K26 (-167.1342, -142.0862) -> (-167.1389, -141.3096)
  curve K27 (-167.3569, -142.9432) -> (-167.1342, -142.0862)
  curve K28 (-167.7647, -144.68) -> (-167.3569, -142.9432)
  curve K29 (-167.5329, -144.7899) -> (-167.7647, -144.68)
  curve K30 (-166.6472, -144.882) -> (-167.5329, -144.7899)
  curve K31 (-165.8859, -143.9973) -> (-166.6472, -144.882)
  curve K32 (-165.6889, -142.9643) -> (-165.8859, -143.9973)
  curve K33 (-166.2734, -142.1671) -> (-165.6889, -142.9643)
  line L55 (-165.761, -141.3443) -> (-166.2734, -142.1671)
  curve K34 (-165.0286, -142.145) -> (-165.761, -141.3443)
  curve K35 (-164.8507, -143.1756) -> (-165.0286, -142.145)
  curve K36 (-165.2019, -144.4594) -> (-164.8507, -143.1756)
  curve K37 (-165.8546, -145.4885) -> (-165.2019, -144.4594)
  curve K38 (-166.5345, -145.9312) -> (-165.8546, -145.4885)
  curve K39 (-167.2695, -145.9366) -> (-166.5345, -145.9312)
  curve K40 (-168.1162, -145.6108) -> (-167.2695, -145.9366)
  line L56 (-169.3113, -145.0751) -> (-168.1162, -145.6108)
  curve K41 (-170.918, -144.4236) -> (-169.3113, -145.0751)
  curve K42 (-171.6545, -144.3655) -> (-170.918, -144.4236)
  line L57 (-171.2348, -143.4294) -> (-171.6545, -144.3655)
  curve K43 (-170.5021, -143.5426) -> (-171.2348, -143.4294)
  curve K44 (-236.4141, -138.56) -> (-233.8745, -138.7564)
  curve K45 (-237.5395, -136.9883) -> (-236.4141, -138.56)
  curve K46 (-237.3306, -134.894) -> (-237.5395, -136.9883)
  curve K47 (-235.4632, -133.5636) -> (-237.3306, -134.894)
  curve K48 (-233.6794, -133.3966) -> (-235.4632, -133.5636)
  curve K49 (-232.4511, -134.0579) -> (-233.6794, -133.3966)
  curve K50 (-231.7211, -135.3037) -> (-232.4511, -134.0579)
  curve K51 (-231.9236, -137.4104) -> (-231.7211, -135.3037)
  curve K52 (-233.8745, -138.7564) -> (-231.9236, -137.4104)
  line L58 (-179.4176, -155.057) -> (-180.1077, -155.6522)
  line L59 (-174.1925, -161.1149) -> (-179.4176, -155.057)
  line L60 (-174.9364, -161.7565) -> (-174.1925, -161.1149)
  line L61 (-176.8004, -159.5953) -> (-174.9364, -161.7565)
  curve K53 (-177.4932, -161.2234) -> (-176.8004, -159.5953)
  curve K54 (-178.4006, -161.7213) -> (-177.4932, -161.2234)
  curve K55 (-179.3912, -161.7759) -> (-178.4006, -161.7213)
  curve K56 (-180.3718, -161.3785) -> (-179.3912, -161.7759)
  curve K57 (-181.2739, -160.6) -> (-180.3718, -161.3785)
  curve K58 (-182.2201, -158.375) -> (-181.2739, -160.6)
  curve K59 (-181.4123, -156.6045) -> (-182.2201, -158.375)
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  point P4 (-200, -120)
  point P41 (-200, -120)
  point P39 (-200, -120)
  point P44 (-200, -120)
  horizontal L17
  coincident P4 P41
  horizontal L19
  coincident P39 P44
  dimension "d481" diameter = 38
  dimension "d482" diameter = 49.4
  dimension "d483" angle L16 L17 = 45
  dimension "d484" angle L18 L19 = 45
extrude "Extrude13" add sketch "Sketch6" along normal blind 4
chamfer "Chamfer7" distance 3.7 Rotate Angle 40
chamfer "Chamfer8" distance 4 Rotate Angle 45
sketch "Suspension Pad" plane through (0, 0, 0) normal (0, 0, 1) x axis (1, 0, 0)
  line L1 (-120, 100) -> (-150, 100)
  line L2 (-120, -100) -> (-120, 100)
  line L3 (-150, -100) -> (-120, -100)
  line L4 (-150, 100) -> (-150, -100)
  line L5 (-165, 0) -> (-150, 0)
  line L6 (-105, 0) -> (-120, 0)
  curve K1 (-120, 100) -> (-120, -100)
  curve K2 (-150, -100) -> (-150, 100)
  line L7 (-135, -98) -> (-135, -100)
  line L8 (-135, 98) -> (-135, 100)
  line L9 (-150, 100) -> (-120, 0)
  line L10 (-150, -100) -> (-120, 0)
  line L11 (-125, 2) -> (-145, 2)
  line L12 (-125, -2) -> (-125, 2)
  line L13 (-145, -2) -> (-125, -2)
  line L14 (-145, 2) -> (-145, -2)
  line L15 (-125, -2) -> (-145, 2)
  line L16 (-145, -2) -> (-125, 2)
  line L17 (-125, 1) -> (-145, 1)
  line L18 (-125, -1) -> (-125, 1)
  line L19 (-145, -1) -> (-125, -1)
  line L20 (-145, 1) -> (-145, -1)
  line L21 (-125, -1) -> (-145, 1)
  line L22 (-145, -1) -> (-125, 1)
  line L23 (-125, 52) -> (-145, 52)
  line L24 (-125, 48) -> (-125, 52)
  line L25 (-145, 48) -> (-125, 48)
  line L26 (-145, 52) -> (-145, 48)
  line L27 (-125, 48) -> (-145, 52)
  line L28 (-145, 48) -> (-125, 52)
  line L29 (-125, 51) -> (-145, 51)
  line L30 (-125, 49) -> (-125, 51)
  line L31 (-145, 49) -> (-125, 49)
  line L32 (-145, 51) -> (-145, 49)
  line L33 (-125, 49) -> (-145, 51)
  line L34 (-145, 49) -> (-125, 51)
  line L35 (-125, -48) -> (-145, -48)
  line L36 (-125, -52) -> (-125, -48)
  line L37 (-145, -52) -> (-125, -52)
  line L38 (-145, -48) -> (-145, -52)
  line L39 (-125, -52) -> (-145, -48)
  line L40 (-145, -52) -> (-125, -48)
  line L41 (-125, -49) -> (-145, -49)
  line L42 (-125, -51) -> (-125, -49)
  line L43 (-145, -51) -> (-125, -51)
  line L44 (-145, -49) -> (-145, -51)
  line L45 (-125, -51) -> (-145, -49)
  line L46 (-145, -51) -> (-125, -49)
  circle C1 centre (-135, -96.5) radius 1.5
  circle C2 centre (-135, 96.5) radius 1.5
  point P6 (-150, 0)
  point P8 (-120, 0)
  point P10 (-135, -100)
  point P11 (-135, -98)
  point P13 (-135, 100)
  point P14 (-135, 98)
  point P20 (-135, 0)
  point P25 (-135, 0)
  point P30 (-135, 50)
  point P35 (-135, 50)
  point P40 (-135, -50)
  point P45 (-135, -50)
  point P2 (-150, 100)
  point P3 (-120, 100)
  point P5 (-150, -100)
  point P7 (-165, 0)
  point P9 (-105, 0)
  point P18 (-125, -2)
  point P19 (-145, -2)
  point P17 (-125, 2)
  point P22 (-125, 1)
  point P23 (-125, -1)
  point P28 (-125, 48)
  point P29 (-145, 48)
  point P27 (-125, 52)
  point P32 (-125, 51)
  point P33 (-125, 49)
  point P38 (-125, -52)
  point P39 (-145, -52)
  point P37 (-125, -48)
  point P43 (-125, -51)
  point P44 (-145, -51)
  point P42 (-125, -49)
  horizontal L1
  vertical L2
  horizontal L3
  vertical L4
  midpoint L4 P6
  perpendicular L4 L5
  midpoint L2 P8
  perpendicular L2 L6
  midpoint L3 P10
  perpendicular L3 L7
  coincident P11 C1
  midpoint L1 P13
  perpendicular L1 L8
  coincident P14 C2
  horizontal L11
  perpendicular L11 L12
  parallel L11 L13
  parallel L12 L14
  coincident L15 P20
  coincident L16 P20
  horizontal L17
  perpendicular L17 L18
  parallel L17 L19
  parallel L18 L20
  coincident L21 P25
  coincident L22 P25
  coincident P20 P25
  horizontal L23
  perpendicular L23 L24
  parallel L23 L25
  parallel L24 L26
  coincident L27 P30
  coincident L28 P30
  midpoint L9 P30
  horizontal L29
  perpendicular L29 L30
  parallel L29 L31
  parallel L30 L32
  coincident L33 P35
  coincident L34 P35
  coincident P30 P35
  horizontal L35
  perpendicular L35 L36
  parallel L35 L37
  parallel L36 L38
  coincident L39 P40
  coincident L40 P40
  midpoint L10 P40
  horizontal L41
  perpendicular L41 L42
  parallel L41 L43
  parallel L42 L44
  coincident L45 P45
  coincident L46 P45
  coincident P40 P45
  dimension "d491" distance P2 P3 = 30
  dimension "d492" distance P2 P5 = 200
  dimension "d493" distance P6 P7 = 15
  dimension "d494" distance P8 P9 = 15
  dimension "d495" distance P10 P11 = 2
  dimension "d496" diameter C1 = 3
  dimension "d497" distance P13 P14 = 2
  dimension "d498" diameter C2 = 3
  dimension "d499" distance P18 P19 = 20
  dimension "d500" distance P17 P18 = 4
  dimension "d501" distance P22 P23 = 2
  dimension "d502" distance P28 P29 = 20
  dimension "d503" distance P27 P28 = 4
  dimension "d504" distance P32 P33 = 2
  dimension "d505" distance P38 P39 = 20
  dimension "d506" distance P37 P38 = 4
  dimension "d507" distance P43 P44 = 20
  dimension "d508" distance P42 P43 = 2
extrude "Extrude5" new body sketch "Suspension Pad" profile of L1 L3 K1 K2 L7 C1 L8 C2 L11 L12 L13 L14 L17 L18 L19 L20 L23 L24 L25 L26 L29 L30 L31 L32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 along normal blind 1.5 bodies "TPU Suspension Pad"
sketch "45cm 1.75mm TPU" plane through (0, 0, 0) normal (0, 0, 1) x axis (1, 0, 0)
  line L1 (-98.25, 180) -> (-100, 180)
  line L2 (-98.25, -270) -> (-98.25, 180)
  line L3 (-100, -270) -> (-98.25, -270)
  line L4 (-100, 180) -> (-100, -270)
  point P2 (-100, 180)
  point P3 (-98.25, 180)
  point P5 (-100, -270)
  horizontal L1
  vertical L2
  horizontal L3
  vertical L4
  dimension "d511" distance P2 P3 = 1.75
  dimension "d512" distance P2 P5 = 450
extrude "Extrude6" new body sketch "45cm 1.75mm TPU" along normal blind 1.75 bodies "45cm 1.75mm Unprinted TPU"
fillet "Fillet1" radius 0.875 (= "( 1.75 / 2 ) * 1 mm")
